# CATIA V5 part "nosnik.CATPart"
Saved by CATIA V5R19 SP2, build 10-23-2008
Part number: nosnik
Material "Steel": density 7860 kg/m3, Young's modulus 2e+11 Pa, Poisson ratio 0.266, thermal expansion 1.17e-05 1/K
Bounding box of the stored display mesh (mm): x -120 to 120, y -15 to 15, z -22.5 to 22.5
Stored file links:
  D:\Prace\Catia\nosnik1\nosnik.CATPart
  C:\Program Files\Dassault Systemes\B19\intel_a\startup\materials\Catalog.CATMaterial
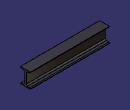
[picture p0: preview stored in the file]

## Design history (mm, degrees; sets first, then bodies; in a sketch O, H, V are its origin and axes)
AxisSystem1: origin (0, 0, 0), X (1, 0, 0), Y (0, 1, 0), Z (0, 0, 1)
Body1 (main body)
  Sketch1 on YZ plane of AxisSystem1, origin (0, 0, 0), H (0, 1, 0), V (0, 0, 1)
    line L1 (2.5, 14.7411) -> (2.5, -14.7411)
    construction line L2 (2.5, -18.4064) -> (-2.5, -18.4064)
    line L3 (-2.5, -14.7411) -> (-2.5, 14.7411)
    construction line L4 (-2.5, 18.4064) -> (2.5, 18.4064)
    point P1 (2.5, 18.4064)
    point P2 (2.5, -18.4064)
    point P3 (-2.5, -18.4064)
    point P4 (-2.5, 18.4064)
    point P5 (0, 20.3479)
    line L5 (15, 22.5) -> (15, 21.3327)
    line L6 (13.1743, 19.3403) -> (6.1514, 18.7258)
    line L7 (-15, 21.3327) -> (-15, 22.5)
    line L8 (-15, 22.5) -> (15, 22.5)
    point P8 (0, -20.3479)
    line L9 (15, -21.3327) -> (15, -22.5)
    line L10 (15, -22.5) -> (-15, -22.5)
    line L11 (-15, -22.5) -> (-15, -21.3327)
    line L12 (-13.1743, -19.3403) -> (-6.1514, -18.7258)
    point P9 (15, -19.5)
    point P11 (-15, -22.5)
    point P12 (-15, -19.5)
    line L13 (6.1514, -18.7258) -> (13.1743, -19.3403)
    line L14 (-6.1514, 18.7258) -> (-13.1743, 19.3403)
    arc A1 centre (6.5, -14.7411) radius 4 from (6.1514, -18.7258) to (2.5, -14.7411) cw
    arc A2 centre (-6.5, -14.7411) radius 4 from (-2.5, -14.7411) to (-6.1514, -18.7258) cw
    arc A3 centre (-6.5, 14.7411) radius 4 from (-2.5, 14.7411) to (-6.1514, 18.7258) ccw
    arc A4 centre (6.5, 14.7411) radius 4 from (6.1514, 18.7258) to (2.5, 14.7411) ccw
    arc A5 centre (13, -21.3327) radius 2 from (15, -21.3327) to (13.1743, -19.3403) ccw
    arc A6 centre (13, 21.3327) radius 2 from (15, 21.3327) to (13.1743, 19.3403) cw
    arc A7 centre (-13, 21.3327) radius 2 from (-15, 21.3327) to (-13.1743, 19.3403) ccw
    arc A8 centre (-13, -21.3327) radius 2 from (-15, -21.3327) to (-13.1743, -19.3403) cw
    distance L3 L1 = 5
    distance L7 L5 = 30
    distance L8 L10 = 45
    angle L12 L10 = 5
    radius A1 = 4
    radius A2 = 4 {= Sketch1.radius(A1)}
    radius A3 = 4 {= Sketch1.radius(A1)}
    radius A4 = 4 {= Sketch1.radius(A1)}
    radius A5 = 2
    radius A6 = 2 {= Sketch1.radius(A5)}
    radius A7 = 2 {= Sketch1.radius(A5)}
    distance P11 P12 = 3
    radius A8 = 2 {= Sketch1.radius(A5)}
    vertical: L1 V, L3 V, L5 V, L7 V, L9 V, L11 V
    horizontal: L2 H, L4 H, L8 H, L10 H
    equidistance: L1 L3 O, L2 L4 O, L5 L7 P5, L6 L8 P5, L9 L11 P8, L10 L12 P8
    coincidence: P5 V, P8 V, P9 L5, L13 P2, L1 P2, L3 P3, L12 P3, L3 P4, L14 P4, L6 P1, L1 P1, L9 P9, L13 P9, L11 P12, L12 P12
    symmetry: L8 L10 H, L14 L12 H, L13 L6 H, L6 L14 V
    tangency: A1 L13, A1 L1, A2 L3, A2 L12, A3 L3, A3 L14, A4 L6, A4 L1, A5 L9, A5 L13, A6 L5, A6 L6, A7 L7, A7 L14, A8 L11, A8 L12
  Pad1: profile Sketch1, direction (1, 0, 0), length 120, mirrored extent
